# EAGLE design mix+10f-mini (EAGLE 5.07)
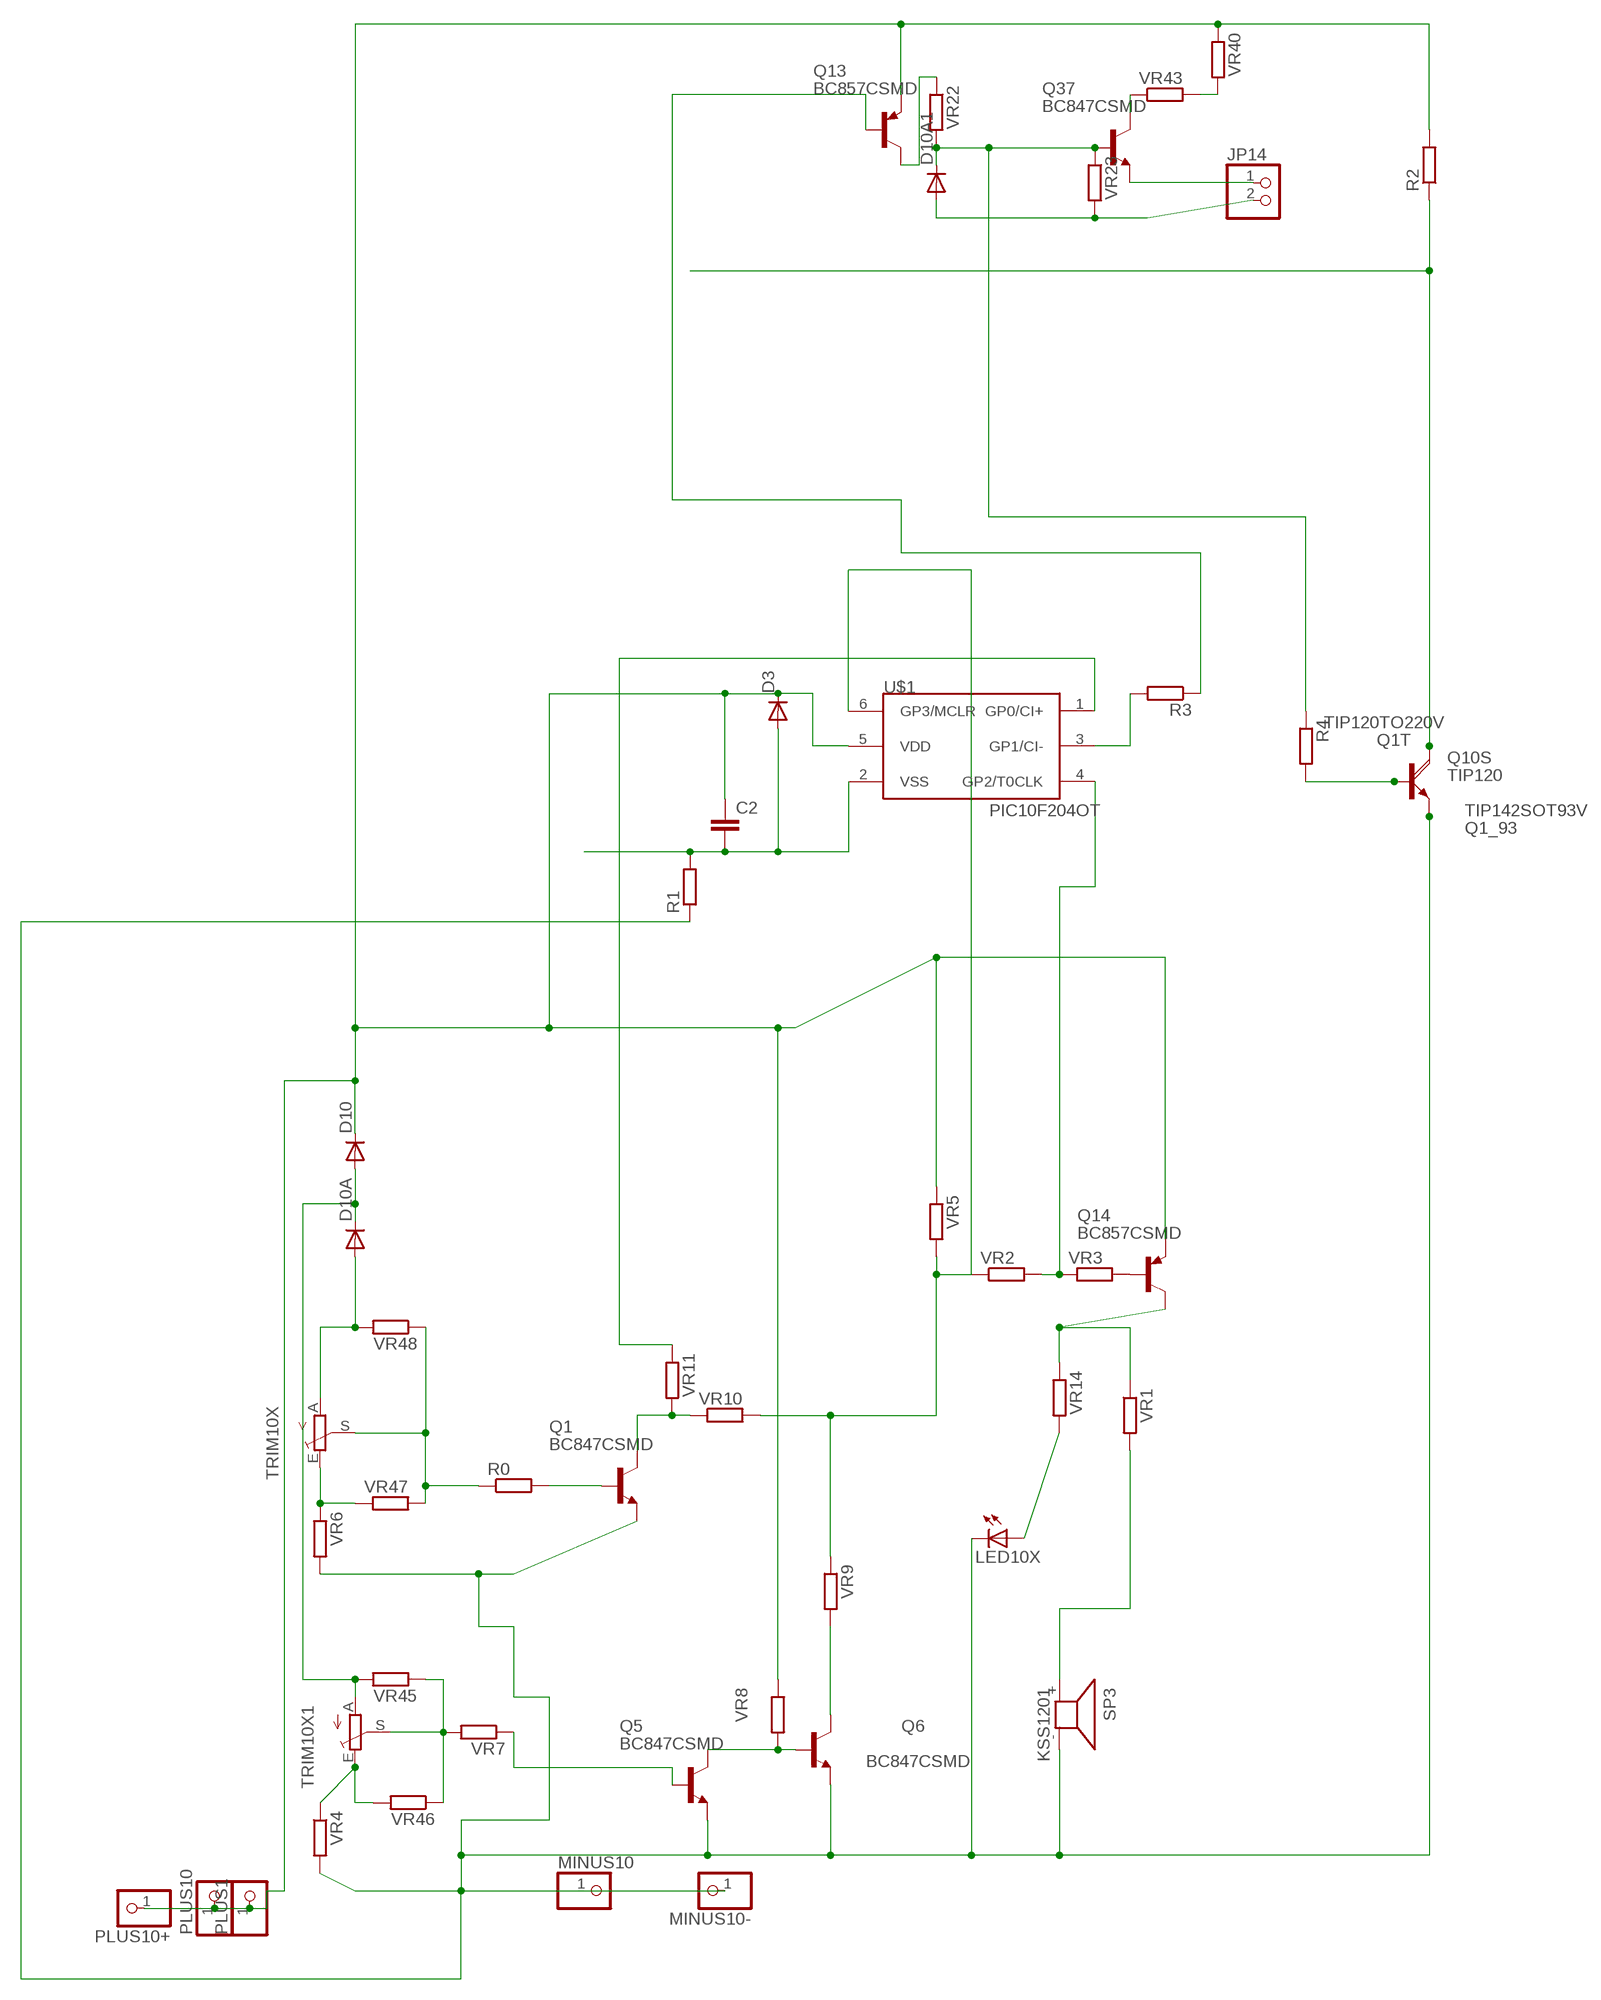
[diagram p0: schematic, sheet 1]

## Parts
C2  C-EUC0805  [C0805]
D3  DIODE-MINIMELF  [MINIMELF]
D10  DIODE-MINIMELF  [MINIMELF]
D10A  DIODE-MINIMELF  [MINIMELF]
D10A1  DIODE-MINIMELF  [MINIMELF]
JP14  PINHD-1X2STR  [1X02]
LED10X  LEDCHIPLED_1206  [CHIPLED_1206]
MINUS10  PINHD-1X14.5MM  [1X4MM5]
MINUS10-  PINHD-1X11X0.4  [1X01]
PLUS1  PINHD-1X14.5MM  [1X4MM5]
PLUS10  PINHD-1X14.5MM  [1X4MM5]
PLUS10+  PINHD-1X11X0.4  [1X01]
Q1  BC847CSMD  [SOT23]
Q1_93  TIP142SOT93V  [SOT93V]
Q1T  TIP120TO220V  [TO220AV]
Q5  BC847CSMD  [SOT23]
Q6  BC847CSMD  [SOT23]
Q10S  TIP120  TIP120DPAK  [D-PAK_TO252AA]
Q13  BC857CSMD  [SOT23-BEC]
Q14  BC857CSMD  [SOT23-BEC]
Q37  BC847CSMD  [SOT23]
R0  R-EU_R0805  [R0805]
R1  R-EU_R0805  [R0805]
R2  R-EU_CERAM85  [CERAM85]
R3  R-EU_R0805  [R0805]
R4  R-EU_R0805  [R0805]
SP3  KSS1201  KSS12017MM  [KSS1202]
TRIM10X  TRIM_EU-S64W  [S64W]
TRIM10X1  TRIM_EU-S64W  [S64W]
U$1  PIC10F204OT  [SOT23-6]
VR1  R-EU_R0805  [R0805]
VR2  R-EU_R0805  [R0805]
VR3  R-EU_R1206  [R1206]
VR4  R-EU_R1206  [R1206]
VR5  R-EU_R0805  [R0805]
VR6  R-EU_R1206  [R1206]
VR7  R-EU_M1206  [M1206]
VR8  R-EU_R1206  [R1206]
VR9  R-EU_R0805  [R0805]
VR10  R-EU_R1206  [R1206]
VR11  R-EU_R0805  [R0805]
VR14  R-EU_R0805  [R0805]
VR22  R-EU_R0805  [R0805]
VR23  R-EU_R0805  [R0805]
VR40  R-EU_R1206  [R1206]
VR43  R-EU_R1206  [R1206]
VR45  R-EU_R1206  [R1206]
VR46  R-EU_R0805  [R0805]
VR47  R-EU_R0805  [R0805]
VR48  R-EU_R0805  [R0805]

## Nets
B: R0.1 TRIM10X.S VR47.2 VR48.1
GP3: U$1.4(GP2/T0CLK) VR2.2 VR3.1
N$1: SP3.+ VR1.2
N$2: Q1.3(C) VR10.1 VR11.2
N$3: Q5.3(C) Q6.1(B) VR8.2
N$4: LED10X.A VR14.2
N$5: Q6.3(C) VR9.2
N$6: U$1.6(GP3/MCLR) VR2.1 VR5.2 VR9.1 VR10.2
N$7: Q1.1(B) R0.2
N$8: Q14.C VR1.1 VR14.1
N$10: Q14.B VR3.2
N$12: U$1.1(GP0/CI+) VR11.1
N$13: D10A1.A JP14.2 VR23.2
N$14: D10A.A TRIM10X.A VR48.2
N$17: D10.A D10A.C TRIM10X1.A VR45.2
N$22: TRIM10X1.S VR7.2 VR45.1 VR46.1
N$23: Q13.B R3.1
N$24: TRIM10X1.E VR4.1 VR46.2
N$25: Q1_93.B Q1T.B Q10S.1(B) R4.2
N$128: TRIM10X.E VR6.1 VR47.1
N$136: JP14.1 Q37.2(E)
N$159: Q13.C VR22.1
N$163: VR40.2 VR43.2
N$164: Q37.3(C) VR43.1
N$165: R3.2 U$1.3(GP1/CI-)
N$168: Q5.1(B) VR7.1
N$179: D10A1.C Q37.1(B) R4.1 VR22.2 VR23.1
PLUS1: C2.1 D3.C D10.C PLUS1.1 PLUS10+.1 PLUS10.1 Q13.E Q14.E R2.2 U$1.5(VDD) VR5.1 VR8.1 VR40.1
Q10C: Q1_93.C Q1T.C Q10S.4(C) R2.1
VSS: LED10X.C MINUS10-.1 MINUS10.1 Q1.2(E) Q1_93.E Q1T.E Q5.2(E) Q6.2(E) Q10S.3(E) R1.1 SP3.- VR4.2 VR6.2
VSS1: C2.2 D3.A R1.2 U$1.2(VSS)

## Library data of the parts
C2 = rcl:C-EU: CAPACITOR, European symbol
D3 D10 D10A D10A1 = diode:DIODE-: DIODE
JP14 = pinhead:PINHD-1X2: PIN HEADER
LED10X = led:LED: LED
MINUS10 MINUS10- PLUS1 PLUS10 PLUS10+ = pinhead:PINHD-1X1: PIN HEADER
Q1 Q5 Q6 Q37 = transistor-npn:BC847*: NPN Transistor
Q1_93 = transistor-power:TIP142: NPN DARLINGTON TRANSISTOR
Q1T Q10S = transistor-power:TIP120: NPN DARLINGTON TRANSISTOR
Q13 Q14 = transistor-pnp:BC857*: PNP Transistror
R0 R1 R3 R4 VR1-VR11 VR14 VR22 VR23 VR40 VR43 VR45-VR48 = rcl-2:R-EU_: RESISTOR, European symbol
R2 = rcl:R-EU_: RESISTOR, European symbol
SP3 = buzzer:KSS1201: SPEAKER
TRIM10X TRIM10X1 = pot:TRIM_EU-: POTENTIOMETER
U$1 = microchip-3:PIC10F2*: uPC nW 0,25/0,5k Program Flash memory Comparator

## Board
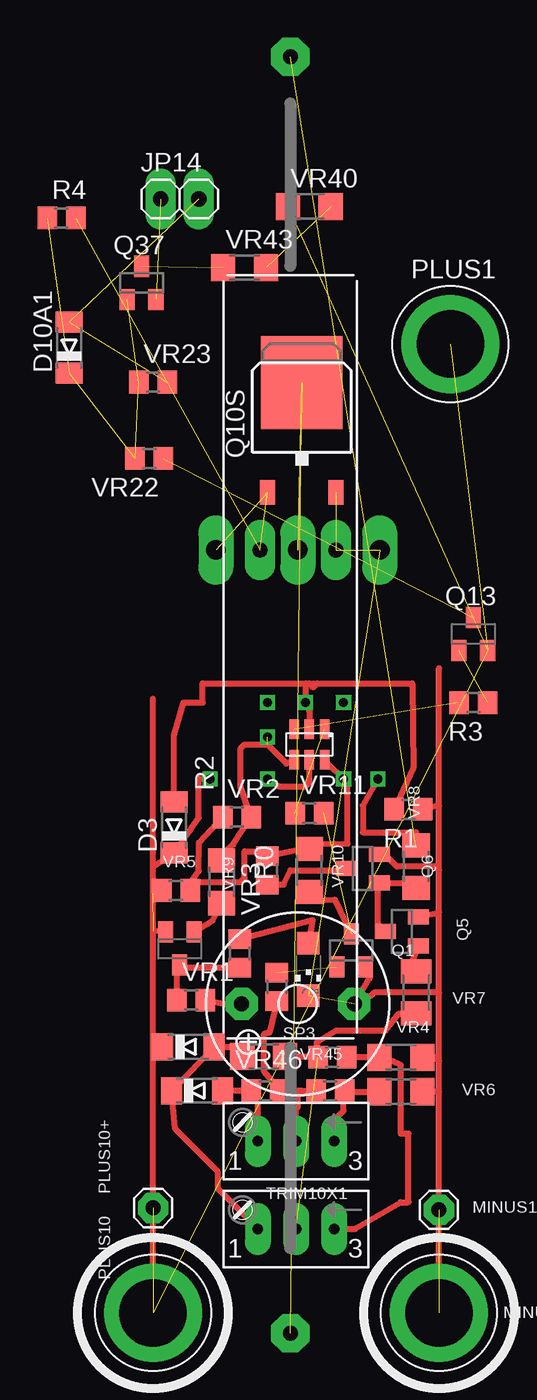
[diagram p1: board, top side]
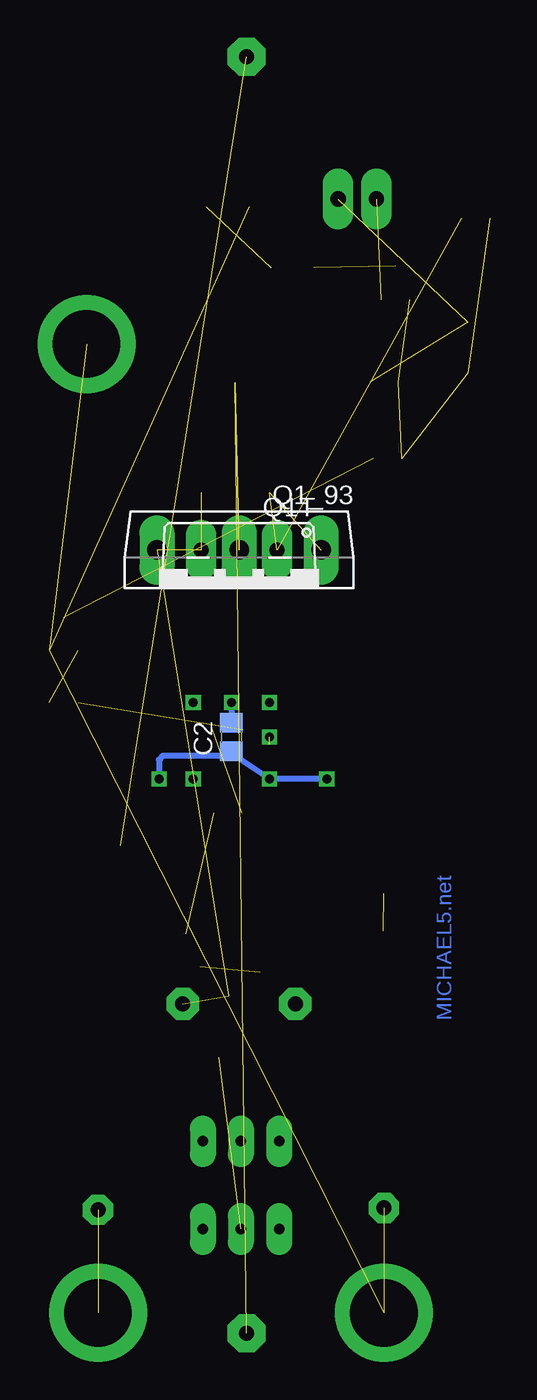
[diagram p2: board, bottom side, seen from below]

No outline drawn. Coordinates in mm, seen from the top.
Copper layers (1*16): Top 0.035mm / dielectric 1.5mm / Bottom 0.035mm
Design rules "default *": minimum track width 8mil, minimum drill 4mil, track to track 8mil, track to pad 8mil, pad to pad 8mil, via to via 8mil, smd to smd 8mil, copper to edge 40mil, drill to drill 8mil, minimum pad ring 20mil, minimum via ring 8mil, stop-mask expansion 4mil, vias tented up to drill 0mil, thermal gap 10mil

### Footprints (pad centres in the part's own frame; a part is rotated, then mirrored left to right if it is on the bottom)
C0805 = smd 1.3 x 1.5: 1 -0.95,0; 2 0.95,0
MINIMELF = smd 1.4 x 1.8: A 1.7,0; C -1.7,0
1X02 = drill 1.016 pad 1.676 long: 1 -1.27,0; 2 1.27,0
CHIPLED_1206 = smd 1.5 x 1.5: A 0,-1.75; C 0,1.75
1X4MM5 = drill 4.5 pad 6.35 round: 1 0,0
1X01 = drill 1 pad 1.676 octagon: 1 0,0
SOT23 = smd 1 x 1.4: 1 -0.95,-1.1; 2 0.95,-1.1; 3 0,1.1
SOT93V = drill 1.3 pad 1.676 long: B -5.461,-2.54; C 0,-2.54; E 5.461,-2.54
TO220AV = drill 1 pad 1.27 long: B -2.54,-2.54; C 0,-2.54; E 2.54,-2.54
D-PAK_TO252AA = smd 1 x 1.6: 1 -2.28,-4.8; 3 2.28,-4.8 | smd 5.4 x 6.2: 4 0,2.5
SOT23-BEC = smd 1 x 1.4: B -0.95,-1.1; C 0,1.1; E 0.95,-1.1
R0805 = smd 1.3 x 1.5: 1 -0.95,0; 2 0.95,0
CERAM85 = drill 1 pad 2.54 octagon: 1 -42.5,0; 2 42.5,0
KSS1202 = drill 1 pad 2.159 octagon: + 3.75,0; - -3.75,0
S64W = drill 0.7 long: A 2.54,1.27; E -2.54,1.27; S 0,1.27
SOT23-6 = smd 0.635 x 1.27: 1 -1.016,-1.016; 2 0,-1.016; 3 1.016,-1.016; 4 1.016,1.016; 5 0,1.016; 6 -1.016,1.016
R1206 = smd 1.6 x 1.803: 1 -1.422,0; 2 1.422,0
M1206 = smd 1.6 x 2: 1 -1.4,0; 2 1.4,0

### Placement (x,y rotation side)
C2  81.28,47.24 90 bottom
D3  72.52,41.21 90 top
D10  73.47,26.61 0 top
D10A  74.04,23.69 0 top
D10A1  65.53,73.15 90 top
JP14  72.9,83.06 0 top
LED10X  81.47,31.75 180 top
MINUS10  90.17,8.89 0 top
MINUS10-  90.17,15.75 0 top
PLUS1  90.93,73.41 0 top
PLUS10  71.12,8.89 0 top
PLUS10+  71.12,15.88 0 top
Q1  84.33,33.02 0 top
Q1_93  80.77,57.15 180 bottom
Q1T  80.77,57.15 180 bottom
Q5  87.69,34.29 90 top
Q6  85.09,38.48 90 top
Q10S  81.03,68.33 0 top
Q13  92.46,54.1 0 top
Q14  72.9,33.15 180 top
Q37  70.36,77.47 0 top
R0  79.38,30.61 90 top
R1  88.14,42.42 180 top
R2  80.26,50.04 90 top
R3  92.46,49.53 180 top
R4  65.02,81.79 0 top
SP3  80.77,29.46 180 top
TRIM10X  80.64,21.59 180 top
TRIM10X1  80.64,15.75 180 top
U$1  81.53,46.74 180 top
VR1  73.66,29.72 0 top
VR2  76.71,41.91 0 top
VR3  75.69,37.59 270 top
VR4  87.63,25.91 0 top
VR5  72.64,37.02 0 top
VR6  87.63,23.62 0 top
VR7  88.65,30.23 270 top
VR8  88.65,38.61 270 top
VR9  78.74,38.35 270 top
VR10  81.53,38.35 90 top
VR11  81.53,42.16 0 top
VR14  76.9,32.83 90 top
VR22  70.87,65.79 180 top
VR23  71.12,70.87 0 top
VR40  81.53,82.55 0 top
VR43  77.22,78.49 0 top
VR45  78.49,25.97 180 top
VR46  83.06,25.91 0 top
VR47  82.93,23.69 180 top
VR48  78.61,23.69 180 top

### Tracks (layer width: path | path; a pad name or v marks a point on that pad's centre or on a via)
B
  Top 0.406: 81.03,23.69 VR48.1 78.49,25.02 78.49,27.43 78.87,27.56 R0.1 | 81.03,23.69 VR47.2 | TRIM10X.S 80.64,22.48 80.77,22.61 80.77,23.43 81.03,23.69
GP3  (via drill 0.6)  (1 unrouted)
  Top 0.406: U$1.4 80.01,45.47 78.74,46.74 77.22,46.74 76.96,46.48 76.96,43.94 VR2.2 76.45,40.07 75.95,39.62 76.2,39.37 VR3.1
  other vias: 78.74,47.24
N$1
  Top 0.406: VR1.2 76.83,29.28 SP3.+
N$2  (1 unrouted)
  Top 0.406: Q1.3 83.23,36.41 81.28,36.32 VR10.1
N$3
  Top 0.406: Q5.3 86.11,34.78 86.11,37.53 Q6.1 88.3,37.53 VR8.2
N$4
  Top 0.406: VR14.2 81.75,35.05 LED10X.A
N$5
  Top 0.406: VR9.2 79.82,37.4 80.26,38.35 83.1,38.35 Q6.3
N$6
  Top 0.406: U$1.6 84.07,44.2 84.07,40.13 81.44,40.12 | 81.44,40.12 VR10.2 | VR5.2 73.34,37.27 73.66,37.59 | 73.66,37.59 76.96,37.59 77.22,37.85 77.22,39.62 78.67,39.62 VR9.1 81.13,39.81 81.44,40.12 | VR2.1 74.17,40.2 74.17,38.29 73.66,37.59
N$7  (1 unrouted)
N$8
  Top 0.406: VR14.1 73.07,31.88 Q14.C 72.71,31.86 VR1.1
N$9  (via drill 0.6)
  other vias: 83.82,44.45
N$10
  Top 0.406: Q14.B 74.72,34.77 75.09,35.03 VR3.2
N$11  (via drill 0.6)
  other vias: 83.82,49.53
N$12  (1 unrouted)
N$13  (2 unrouted)
N$14
  Top 0.406: TRIM10X.A 78.11,23.62 VR48.2 D10A.A
N$17
  Top 0.406: VR45.2 77.6,26.61 D10.A 72.59,23.91 D10A.C 72.59,21.13 75.44,18.29 75.44,17.14 TRIM10X1.A
N$22  (1 unrouted)
  Top 0.406: VR7.2 87.5,28.83 86.61,27.69 83.31,27.69 82.04,26.92 82.04,25.97 VR46.1 82.04,25.97 VR45.1
N$23  (1 unrouted)
N$24
  Top 0.406: TRIM10X1.E 84.58,14.48 87.63,16.26 88.14,16.26 88.14,20.83 87.63,20.83 87.63,25.4 87.12,25.65 86.46,25.65 VR4.1 VR46.2
N$25  (3 unrouted)
N$128
  Top 0.406: TRIM10X.E 83.19,21.72 83.82,22.35 83.82,23.62 VR47.1 83.82,23.62 VR6.1
N$136  (1 unrouted)
N$159  (1 unrouted)
N$163  (1 unrouted)
N$164  (1 unrouted)
N$165  (1 unrouted)
N$168
  Top 0.406: Q5.1 88.28,31.99 VR7.1
N$179  (4 unrouted)
PLUS1  (via drill 0.6)  (6 unrouted)
  Top 0.406: PLUS10.1 71.12,26.61 | 71.12,26.61 D10.C | Q14.E 71.16,34.33 | VR8.1 88.65,40.89 85.09,40.89 85.09,42.67 v86.11,44.45 | U$1.5 81.53,44.2 81.28,43.94 79.5,43.94 v78.74,44.45 | v74.93,44.45 74.17,44.45 74.17,41.85 73.6,41.02 D3.C 71.12,38.62 | 71.12,26.61 71.12,36.83 | 71.12,36.83 71.12,38.62 | 71.12,38.62 71.12,49.78 | VR5.1 71.31,37.02 71.12,36.83
  Bottom 0.406: v86.11,44.45 86.11,45.72 85.85,45.97 81.03,45.97 | 81.03,45.97 v78.74,44.45 v74.93,44.45 | C2.1 80.91,46.29 80.91,45.9 81.03,45.9 81.03,45.97
Q10C  (3 unrouted)
VDF  (via drill 0.6)
  other vias: 78.74,49.53
VSS  (5 unrouted)
  Top 0.406: 90.17,30.23 90.17,35.56 | 90.17,35.56 90.17,38.35 | 90.17,38.35 90.17,42.67 | 90.17,42.67 90.17,51.82 | MINUS10.1 90.17,23.62 | 90.17,23.62 90.17,25.65 | 90.17,25.65 90.17,30.23 | 90.17,30.23 85.85,30.23 85.6,29.97 85.34,29.97 85.34,29.46 SP3.- 85.54,31.16 Q1.2 | Q5.2 90.1,35.49 90.17,35.56 | VR4.2 89.92,25.91 90.17,25.65 | 90.17,23.62 VR6.2 | 90.17,42.67 R1.1 | Q6.2 86.55,39.43 87.38,38.61 89.92,38.61 90.17,38.35
VSS1  (via drill 0.6)
  Top 0.406: R1.2 88.46,45.15 88.39,50.8 82.04,50.8 | 81.53,50.8 82.04,50.8 | 81.28,50.8 74.42,50.8 74.42,49.53 73.15,49.53 72.52,47.37 D3.A | 81.28,50.8 81.53,50.8 | 81.53,50.8 81.79,50.55 82.04,50.8 | U$1.2 81.53,48.96 v81.28,49.53 81.28,50.8
  Bottom 0.406: v81.28,49.53 C2.2

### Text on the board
Bottom: MICHAEL5.net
